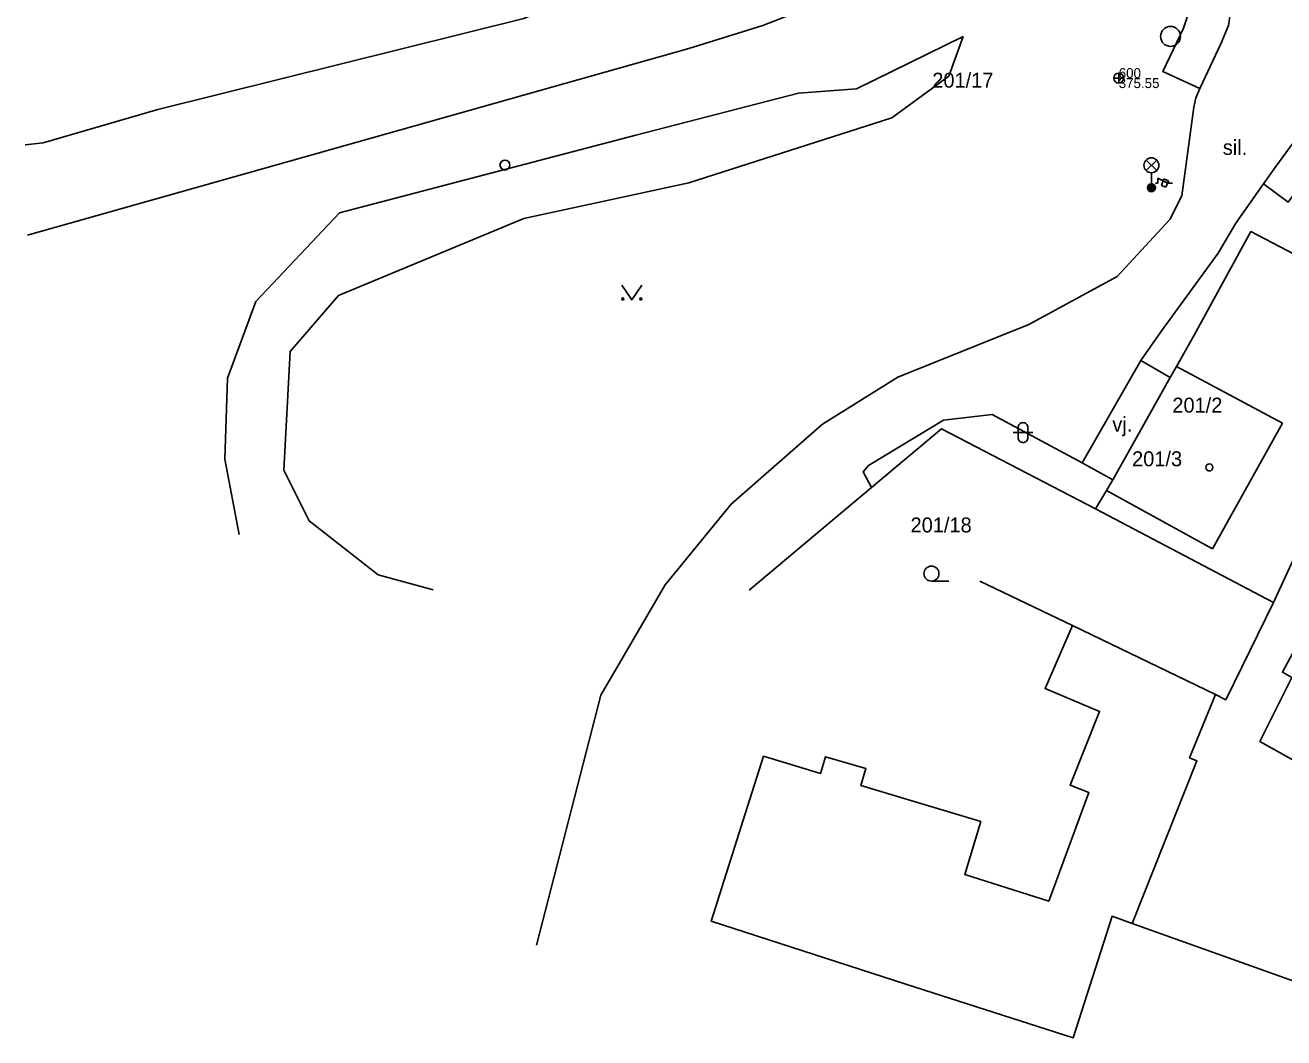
# Model space of a CAD drawing. Extents: x -836568 to -836015, y -1070547 to -1070212.
# Drawn here: x -836562 to -836498.9, y -1070372.9 to -1070322.1 of the extents above; entities that cross this region are included whole.
import ezdxf

# ---------------------------------------------------------------- set-up
doc = ezdxf.new("R2010")
doc.units = 0
for name, color, linetype in [('BodPole_mer', 7, 'Continuous'), ('BodPole_popis', 7, 'Continuous'), ('Budovy_hranice', 7, 'Continuous'), ('Budovy_kody', 7, 'Continuous'), ('Doprava_hranice', 7, 'Continuous'), ('Doprava_kody', 7, 'Continuous'), ('OstPloch_kody', 7, 'Continuous'), ('PovrZnIS_body', 7, 'Continuous'), ('PovrZnIS_hranice', 7, 'Continuous'), ('PovrZnIS_kody', 7, 'Continuous'), ('RuianPar_popis', 7, 'Continuous'), ('Stavby_linie', 7, 'Continuous'), ('Zelen_kody', 7, 'Continuous')]:
    doc.layers.add(name, color=color, linetype=linetype)

msp = doc.modelspace()

# ---------------------------------------------------------------- linework, layer by layer
at = {"layer": 'BodPole_mer'}
for p, q in [((-836525.05, -1070322.08), (-836525.05, -1070322.08)), ((-836515, -1070322.63), (-836515, -1070322.63)), ((-836504.6, -1070322.63), (-836504.6, -1070322.63)), ((-836503.95, -1070322.21), (-836503.95, -1070322.21)), ((-836501.69, -1070322.09), (-836501.69, -1070322.09)), ((-836528.75, -1070323.23), (-836528.75, -1070323.23)), ((-836502.08, -1070323), (-836502.08, -1070323)), ((-836504.98, -1070324.39), (-836504.98, -1070324.39)), ((-836515.72, -1070324.62), (-836515.72, -1070324.62)), ((-836507.2, -1070324.72), (-836507.2, -1070324.72)), ((-836523.26, -1070325.47), (-836523.26, -1070325.47)), ((-836520.35, -1070325.26), (-836520.35, -1070325.26)), ((-836503.34, -1070325.71), (-836503.34, -1070325.71)), ((-836503.14, -1070325.25), (-836503.14, -1070325.25)), ((-836503.44, -1070326.18), (-836503.44, -1070326.18)), ((-836518.57, -1070326.72), (-836518.57, -1070326.72)), ((-836531.42, -1070327.59), (-836531.42, -1070327.59)), ((-836537.98, -1070329.08), (-836537.98, -1070329.08)), ((-836499.32, -1070329.15), (-836499.32, -1070329.15)), ((-836528.76, -1070329.97), (-836528.76, -1070329.97)), ((-836505.56, -1070330.22), (-836505.56, -1070330.22)), ((-836505.06, -1070330.1), (-836505.06, -1070330.1)), ((-836504.93, -1070329.78), (-836504.93, -1070329.78)), ((-836504.83, -1070330.19), (-836504.83, -1070330.19)), ((-836504.7, -1070329.87), (-836504.7, -1070329.87)), ((-836499.94, -1070330.03), (-836499.94, -1070330.03)), ((-836504.04, -1070330.63), (-836504.04, -1070330.63)), ((-836537.04, -1070331.76), (-836537.04, -1070331.76)), ((-836504.64, -1070331.81), (-836504.64, -1070331.81)), ((-836501.33, -1070331.99), (-836501.33, -1070331.99)), ((-836500.57, -1070332.42), (-836500.57, -1070332.42)), ((-836502.21, -1070333.5), (-836502.21, -1070333.5)), ((-836507.28, -1070334.68), (-836507.28, -1070334.68)), ((-836511.7, -1070337.08), (-836511.7, -1070337.08)), ((-836505.09, -1070337.45), (-836505.09, -1070337.45)), ((-836503.41, -1070337.61), (-836503.41, -1070337.61)), ((-836506.09, -1070338.88), (-836506.09, -1070338.88)), ((-836518.27, -1070339.72), (-836518.27, -1070339.72)), ((-836504.3, -1070339.18), (-836504.3, -1070339.18)), ((-836504.62, -1070339.74), (-836504.62, -1070339.74)), ((-836513.54, -1070341.59), (-836513.54, -1070341.59)), ((-836522.06, -1070342.08), (-836522.06, -1070342.08)), ((-836515.98, -1070341.87), (-836515.98, -1070341.87)), ((-836498.99, -1070342.03), (-836498.99, -1070342.03)), ((-836516.09, -1070342.31), (-836516.09, -1070342.31)), ((-836509.04, -1070344.01), (-836509.04, -1070344.01)), ((-836520.02, -1070344.47), (-836520.02, -1070344.47)), ((-836519.75, -1070344.15), (-836519.75, -1070344.15)), ((-836519.59, -1070345.25), (-836519.59, -1070345.25)), ((-836507.5, -1070344.87), (-836507.5, -1070344.87)), ((-836507.81, -1070345.41), (-836507.81, -1070345.41)), ((-836508.36, -1070346.32), (-836508.36, -1070346.32)), ((-836502.49, -1070348.34), (-836502.49, -1070348.34)), ((-836514.16, -1070349.95), (-836514.16, -1070349.95)), ((-836499.44, -1070351.03), (-836499.44, -1070351.03)), ((-836509.51, -1070352.17), (-836509.51, -1070352.17)), ((-836498.99, -1070354.52), (-836498.99, -1070354.52)), ((-836510.89, -1070355.34), (-836510.89, -1070355.34)), ((-836502.34, -1070355.64), (-836502.34, -1070355.64)), ((-836501.82, -1070355.9), (-836501.82, -1070355.9)), ((-836508.16, -1070356.49), (-836508.16, -1070356.49)), ((-836500.13, -1070357.99), (-836500.13, -1070357.99)), ((-836503.65, -1070358.81), (-836503.65, -1070358.81)), ((-836503.28, -1070358.96), (-836503.28, -1070358.96))]:
    msp.add_line(p, q, dxfattribs=at)
at = {"layer": 'Budovy_hranice'}
for p, q in [((-836507.81, -1070345.41), (-836502.49, -1070348.34)), ((-836491.71, -1070372.41), (-836506.52, -1070367.12))]:
    msp.add_line(p, q, dxfattribs=at)
for points in [[(-836504.3, -1070339.18), (-836504.62, -1070339.74), (-836507.5, -1070344.87), (-836507.81, -1070345.41)], [(-836502.49, -1070348.34), (-836498.99, -1070342.03), (-836504.3, -1070339.18)], [(-836486.05, -1070361.8), (-836493.56, -1070357.58), (-836495.41, -1070361.07), (-836497.11, -1070360.09), (-836496.94, -1070359.76), (-836500.13, -1070357.99), (-836498.52, -1070354.78), (-836498.99, -1070354.52), (-836494.45, -1070346.05), (-836491.04, -1070347.91), (-836489.68, -1070345.25), (-836482.72, -1070349.16), (-836484.08, -1070351.72), (-836481.46, -1070353.16), (-836481.83, -1070353.85), (-836486.05, -1070361.8)], [(-836506.52, -1070367.12), (-836507.53, -1070366.76), (-836509.49, -1070372.86), (-836517.87, -1070370.16), (-836527.63, -1070367.01), (-836525.81, -1070361.26), (-836525.01, -1070358.74), (-836522.15, -1070359.6), (-836521.9, -1070358.76), (-836519.88, -1070359.35), (-836520.14, -1070360.2), (-836514.12, -1070362.01), (-836514.92, -1070364.66), (-836510.71, -1070366), (-836508.7, -1070360.55), (-836509.64, -1070360.18), (-836508.16, -1070356.49), (-836510.89, -1070355.34), (-836509.51, -1070352.17), (-836502.34, -1070355.64), (-836503.65, -1070358.81), (-836503.28, -1070358.96), (-836506.52, -1070367.12)]]:
    msp.add_lwpolyline(points, dxfattribs=at)
at = {"layer": 'Budovy_kody'}
msp.add_circle((-836502.65, -1070344.25), 0.175, dxfattribs=at)
at = {"layer": 'Doprava_hranice'}
for p, q in [((-836525.05, -1070322.08), (-836528.75, -1070323.23)), ((-836515.72, -1070324.62), (-836515, -1070322.63)), ((-836561.92, -1070332.6), (-836528.75, -1070323.23)), ((-836506.09, -1070338.88), (-836504.62, -1070339.74)), ((-836509.04, -1070344.01), (-836507.5, -1070344.87))]:
    msp.add_line(p, q, dxfattribs=at)
for points in [[(-836525.05, -1070322.08), (-836520.89, -1070320.45), (-836511.44, -1070316.88), (-836510.57, -1070316.45), (-836509.63, -1070316.04), (-836508.64, -1070315.79), (-836507.63, -1070315.7), (-836506.6, -1070315.77), (-836505.63, -1070316.02), (-836504.69, -1070316.45), (-836503.83, -1070316.95), (-836503.04, -1070317.62), (-836502.41, -1070318.42), (-836501.96, -1070319.33), (-836501.67, -1070320.32), (-836501.58, -1070321.32), (-836501.69, -1070322.09), (-836502.08, -1070323), (-836503.14, -1070325.25), (-836503.34, -1070325.71), (-836503.44, -1070326.18), (-836504.04, -1070330.63), (-836504.64, -1070331.81)], [(-836503.14, -1070325.25), (-836504.98, -1070324.39), (-836503.95, -1070322.21), (-836503.63, -1070321.24), (-836503.78, -1070320.23), (-836504.25, -1070319.33), (-836505.01, -1070318.63), (-836505.89, -1070318.14), (-836506.85, -1070317.82), (-836507.86, -1070317.76), (-836508.87, -1070317.96), (-836509.8, -1070318.36), (-836510.52, -1070318.68), (-836511.44, -1070316.88)], [(-836530.36, -1070319.04), (-836537.03, -1070321.73), (-836555.38, -1070326.29), (-836561.14, -1070327.96), (-836562.04, -1070328.06)], [(-836515, -1070322.63), (-836520.35, -1070325.26), (-836523.26, -1070325.47), (-836531.42, -1070327.59), (-836546.27, -1070331.48), (-836550.47, -1070335.93), (-836551.89, -1070339.77), (-836552.03, -1070343.83), (-836551.31, -1070347.61)], [(-836541.58, -1070350.39), (-836544.34, -1070349.63), (-836547.79, -1070346.93), (-836549.07, -1070344.38), (-836548.75, -1070338.43), (-836546.32, -1070335.63), (-836537.04, -1070331.76), (-836528.76, -1070329.97), (-836518.57, -1070326.72), (-836515.72, -1070324.62)], [(-836498.45, -1070327.97), (-836499.32, -1070329.15), (-836499.94, -1070330.03), (-836501.33, -1070331.99), (-836502.21, -1070333.5)], [(-836499.94, -1070330.03), (-836498.7, -1070330.94), (-836497.65, -1070329.5), (-836496.1, -1070330.6)], [(-836536.4, -1070368.21), (-836533.17, -1070355.68), (-836529.95, -1070350.14), (-836526.64, -1070346.09), (-836522.06, -1070342.08), (-836518.27, -1070339.72), (-836511.7, -1070337.08), (-836507.28, -1070334.68), (-836504.64, -1070331.81)], [(-836502.21, -1070333.5), (-836505.09, -1070337.45), (-836506.09, -1070338.88), (-836509.04, -1070344.01), (-836513.54, -1070341.59), (-836515.98, -1070341.87)], [(-836519.59, -1070345.25), (-836520.02, -1070344.47), (-836519.75, -1070344.15), (-836515.98, -1070341.87)]]:
    msp.add_lwpolyline(points, dxfattribs=at)
at = {"layer": 'OstPloch_kody'}
for p, q in [((-836512.25, -1070342.75), (-836512.25, -1070342.25)), ((-836511.75, -1070342.25), (-836511.75, -1070342.75)), ((-836512.5, -1070342.5), (-836511.5, -1070342.5)), ((-836515.715, -1070349.95), (-836516.59, -1070349.95))]:
    msp.add_line(p, q, dxfattribs=at)
for points in [[(-836512, -1070342), (-836512.045, -1070342.004), (-836512.092, -1070342.018), (-836512.137, -1070342.041), (-836512.177, -1070342.073), (-836512.209, -1070342.113), (-836512.232, -1070342.158), (-836512.246, -1070342.205), (-836512.25, -1070342.25)], [(-836512, -1070342), (-836511.955, -1070342.004), (-836511.908, -1070342.018), (-836511.863, -1070342.041), (-836511.823, -1070342.073), (-836511.791, -1070342.113), (-836511.768, -1070342.158), (-836511.754, -1070342.205), (-836511.75, -1070342.25)], [(-836512, -1070343), (-836512.045, -1070342.996), (-836512.092, -1070342.982), (-836512.137, -1070342.959), (-836512.177, -1070342.927), (-836512.209, -1070342.887), (-836512.232, -1070342.842), (-836512.246, -1070342.795), (-836512.25, -1070342.75)], [(-836511.75, -1070342.75), (-836511.754, -1070342.795), (-836511.768, -1070342.842), (-836511.791, -1070342.887), (-836511.823, -1070342.927), (-836511.863, -1070342.959), (-836511.908, -1070342.982), (-836511.955, -1070342.996), (-836512, -1070343)]]:
    msp.add_lwpolyline(points, dxfattribs=at)
msp.add_ellipse((-836516.59, -1070349.575), major_axis=(0.375, 0), ratio=0.999999, dxfattribs=at)
at = {"layer": 'PovrZnIS_body'}
for p, q in [((-836507.2, -1070324.97), (-836507.2, -1070324.47)), ((-836506.95, -1070324.72), (-836507.45, -1070324.72)), ((-836505.825, -1070329.36), (-836505.295, -1070328.83)), ((-836505.825, -1070328.83), (-836505.295, -1070329.36)), ((-836505.56, -1070330.02), (-836505.56, -1070329.47))]:
    msp.add_line(p, q, dxfattribs=at)
for centre, radius in [((-836504.6, -1070322.63), 0.5), ((-836507.2, -1070324.72), 0.25), ((-836537.98, -1070329.08), 0.25)]:
    msp.add_circle(centre, radius, dxfattribs=at)
for centre, major_axis in [((-836505.56, -1070329.095), (0.375, 0)), ((-836505.56, -1070330.22), (0.2, 0)), ((-836505.556, -1070330.22), (0.125, 0)), ((-836505.556, -1070330.22), (0.05, 0))]:
    msp.add_ellipse(centre, major_axis=major_axis, ratio=0.999998, dxfattribs=at)
at = {"layer": 'PovrZnIS_hranice'}
for p, q in [((-836505.06, -1070330.1), (-836504.93, -1070329.78)), ((-836505.06, -1070330.1), (-836504.83, -1070330.19)), ((-836504.7, -1070329.87), (-836504.93, -1070329.78)), ((-836504.83, -1070330.19), (-836504.7, -1070329.87))]:
    msp.add_line(p, q, dxfattribs=at)
at = {"layer": 'PovrZnIS_kody'}
for p, q in [((-836505.35, -1070329.99), (-836505.24, -1070329.99)), ((-836505.24, -1070329.99), (-836505.24, -1070329.74)), ((-836505.24, -1070329.74), (-836504.74, -1070329.99)), ((-836504.74, -1070329.99), (-836504.495, -1070329.99))]:
    msp.add_line(p, q, dxfattribs=at)
at = {"layer": 'RuianPar_popis'}
for p, q in [((-836516.55, -1070325.2), (-836516.55, -1070325.2)), ((-836504.51, -1070341.5), (-836504.51, -1070341.5)), ((-836506.53, -1070344.19), (-836506.53, -1070344.19)), ((-836517.64, -1070347.51), (-836517.64, -1070347.51))]:
    msp.add_line(p, q, dxfattribs=at)
at = {"layer": 'Stavby_linie'}
for p, q in [((-836503.41, -1070337.61), (-836504.3, -1070339.18)), ((-836507.81, -1070345.41), (-836508.36, -1070346.32)), ((-836508.36, -1070346.32), (-836499.44, -1070351.03)), ((-836509.51, -1070352.17), (-836514.16, -1070349.95))]:
    msp.add_line(p, q, dxfattribs=at)
for points in [[(-836493.1, -1070336.59), (-836496.65, -1070334.47), (-836500.57, -1070332.42), (-836503.41, -1070337.61)], [(-836502.34, -1070355.64), (-836501.82, -1070355.9), (-836499.44, -1070351.03), (-836494.05, -1070339.35), (-836493.01, -1070337.1)], [(-836525.73, -1070350.4), (-836519.59, -1070345.25), (-836516.09, -1070342.31), (-836508.36, -1070346.32)]]:
    msp.add_lwpolyline(points, dxfattribs=at)
at = {"layer": 'Zelen_kody'}
msp.add_lwpolyline([(-836531.12, -1070335.1), (-836531.62, -1070335.85), (-836532.12, -1070335.1)], dxfattribs=at)
for centre in [(-836532.069, -1070335.8), (-836531.169, -1070335.8)]:
    msp.add_circle(centre, 0.05, dxfattribs=at)

# ---------------------------------------------------------------- texts
at = {"layer": 'BodPole_popis'}
for s, p in [('600', (-836507.2, -1070324.72)), ('375.55', (-836507.2, -1070325.22))]:
    msp.add_text(s, height=0.5, dxfattribs=at).set_placement(p)
at = {"layer": 'Doprava_kody'}
for s, p in [('sil.', (-836501.98, -1070328.57)), ('vj.', (-836507.52, -1070342.46))]:
    msp.add_text(s, height=0.75, dxfattribs=at).set_placement(p)
at = {"layer": 'RuianPar_popis'}
for s, p in [('201/17', (-836516.55, -1070325.2)), ('201/2', (-836504.51, -1070341.5)), ('201/3', (-836506.53, -1070344.19)), ('201/18', (-836517.64, -1070347.51))]:
    msp.add_text(s, height=0.75, dxfattribs=at).set_placement(p)

doc.saveas('drawing.dxf')
